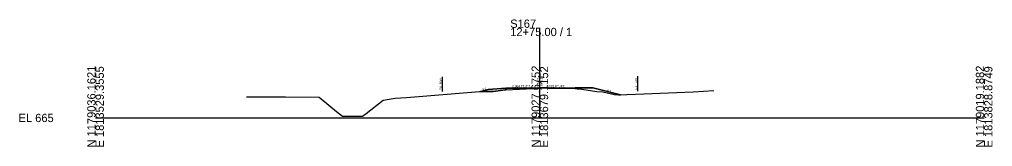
# Model space of a CAD drawing. Extents: x -26 to 6803, y -10 to 1023.
# Drawn here: x 3874.3 to 4202.8, y -9.7 to 33.3 of the extents above; entities that cross this region are included whole.
import ezdxf

# ---------------------------------------------------------------- set-up
doc = ezdxf.new("R2010")
doc.units = 0
for name, color, linetype in [('Default', 7, 'Continuous'), ('RD_EX_RW', 7, 'Continuous'), ('RD_GPK_XS_Cell', 7, 'Continuous'), ('RD_XS_EarthShd', 7, 'Continuous'), ('RD_XS_ExGround', 7, 'Continuous'), ('RD_XS_Misc_Line', 7, 'Continuous'), ('RD_XS_Pave', 7, 'Continuous'), ('RD_XS_TieSlope', 7, 'Continuous'), ('RD_XS_TX_Elev_EX', 7, 'Continuous'), ('RD_XS_TX_Elev_PR', 7, 'Continuous'), ('RD_XS_TX_Slope', 7, 'Continuous')]:
    doc.layers.add(name, color=color, linetype=linetype)

msp = doc.modelspace()

# ---------------------------------------------------------------- linework, layer by layer
at = {"layer": 'Default'}
for p, q in [((4038.52, 10.07), (4050, 10.12)), ((4050, 10.12), (4061.87, 10.14))]:
    msp.add_line(p, q, dxfattribs=at)
at = {"layer": 'RD_EX_RW'}
for p, q in [((4017, 13.91), (4017, 8.91)), ((4083, 14.09), (4083, 9.09))]:
    msp.add_line(p, q, dxfattribs=at)
at = {"layer": 'RD_GPK_XS_Cell'}
for p, q in [((4050, 0), (4050, 30.49)), ((3900, 0), (4050, 0)), ((4050, 0), (4200, 0))]:
    msp.add_line(p, q, dxfattribs=at)
at = {"layer": 'RD_XS_EarthShd'}
for p, q in [((4038.52, 10.07), (4032.52, 9.57)), ((4061.87, 10.14), (4067.87, 10.15))]:
    msp.add_line(p, q, dxfattribs=at)
at = {"layer": 'RD_XS_ExGround'}
msp.add_lwpolyline([(3950.93, 7.12), (3964.18, 7.11), (3975.5, 7.03), (3981.3, 2.14), (3983.41, 0.61), (3984.05, 0.61), (3987.19, 0.6), (3989.65, 0.62), (3990.1, 0.62), (3991.41, 1.46), (3997.14, 6.02), (4001.12, 6.66), (4004.95, 6.92), (4029.62, 8.94), (4034.2, 8.94), (4037.56, 9.36), (4038.52, 9.51), (4047.71, 10), (4050, 10.12), (4050.85, 10.16), (4053.57, 10.11), (4061.87, 9.96), (4062.58, 9.88), (4064.21, 9.69), (4069.22, 8.95), (4071.24, 8.78), (4075.26, 7.97), (4076.52, 7.76), (4085.13, 8.19), (4101.8, 8.78), (4108.71, 9.23)], dxfattribs=at)
at = {"layer": 'RD_XS_Misc_Line'}
for points in [[(4037.56, 9.36), (4038.52, 9.51), (4038.52, 10.07), (4032.52, 9.57), (4030.02, 8.94), (4034.2, 8.94)], [(4037.56, 9.36), (4038.52, 9.51), (4038.52, 10.07), (4032.52, 9.57), (4030.02, 8.94), (4034.2, 8.94)], [(4037.56, 9.36), (4038.52, 9.51), (4038.52, 10.07), (4032.52, 9.57), (4030.02, 8.94), (4034.2, 8.94)], [(4038.52, 10.07), (4038.52, 9.51), (4037.56, 9.36), (4034.2, 8.94), (4030.02, 8.94), (4032.52, 9.57)], [(4038.52, 10.07), (4038.52, 9.51), (4037.56, 9.36), (4034.2, 8.94), (4030.02, 8.94), (4032.52, 9.57)], [(4047.71, 10), (4050, 10.12), (4038.52, 10.07), (4038.52, 9.51)], [(4047.71, 10), (4050, 10.12), (4038.52, 10.07), (4038.52, 9.51)], [(4047.71, 10), (4050, 10.12), (4038.52, 10.07), (4038.52, 9.51)], [(4038.52, 10.07), (4038.52, 9.51), (4047.71, 10), (4050, 10.12)], [(4038.52, 10.07), (4038.52, 9.51), (4047.71, 10), (4050, 10.12)], [(4050, 10.12), (4050.85, 10.16), (4052.79, 10.12)], [(4050, 10.12), (4050.85, 10.16), (4052.79, 10.12)], [(4050, 10.12), (4050.85, 10.16), (4052.79, 10.12)], [(4050.85, 10.16), (4052.79, 10.12), (4050, 10.12)], [(4050.85, 10.16), (4052.79, 10.12), (4050, 10.12)], [(4052.79, 10.12), (4061.87, 10.14), (4061.87, 9.96), (4053.57, 10.11)], [(4052.79, 10.12), (4061.87, 10.14), (4061.87, 9.96), (4053.57, 10.11)], [(4052.79, 10.12), (4061.87, 10.14), (4061.87, 9.96), (4053.57, 10.11)], [(4052.79, 10.12), (4053.57, 10.11), (4061.87, 9.96), (4061.87, 10.14)], [(4052.79, 10.12), (4053.57, 10.11), (4061.87, 9.96), (4061.87, 10.14)], [(4075.26, 7.97), (4076.52, 7.76), (4077.26, 7.8), (4067.87, 10.15), (4061.87, 10.14), (4061.87, 9.96), (4062.58, 9.88), (4064.21, 9.69), (4069.22, 8.95), (4071.24, 8.78)], [(4075.26, 7.97), (4076.52, 7.76), (4077.26, 7.8), (4067.87, 10.15), (4061.87, 10.14), (4061.87, 9.96), (4062.58, 9.88), (4064.21, 9.69), (4069.22, 8.95), (4071.24, 8.78)], [(4075.26, 7.97), (4076.52, 7.76), (4077.26, 7.8), (4067.87, 10.15), (4061.87, 10.14), (4061.87, 9.96), (4062.58, 9.88), (4064.21, 9.69), (4069.22, 8.95), (4071.24, 8.78)], [(4061.87, 9.96), (4062.58, 9.88), (4064.21, 9.69), (4069.22, 8.95), (4071.24, 8.78), (4075.26, 7.97), (4076.52, 7.76), (4077.26, 7.8), (4067.87, 10.15), (4061.87, 10.14)], [(4061.87, 9.96), (4062.58, 9.88), (4064.21, 9.69), (4069.22, 8.95), (4071.24, 8.78), (4075.26, 7.97), (4076.52, 7.76), (4077.26, 7.8), (4067.87, 10.15), (4061.87, 10.14)]]:
    msp.add_lwpolyline(points, close=True, dxfattribs=at)
at = {"layer": 'RD_XS_Pave'}
for p, q in [((4038.52, 10.07), (4038.52, 9.51)), ((4061.87, 9.96), (4061.87, 10.14))]:
    msp.add_line(p, q, dxfattribs=at)
at = {"layer": 'RD_XS_TieSlope'}
for p, q in [((4067.87, 10.15), (4077.26, 7.8)), ((4032.52, 9.57), (4030.02, 8.94))]:
    msp.add_line(p, q, dxfattribs=at)

# ---------------------------------------------------------------- texts
at = {"layer": 'RD_EX_RW'}
for p in [(4016.94, 9.43), (4082.94, 9.61)]:
    msp.add_text('EX. R/W', height=0.75, rotation=90, dxfattribs=at).set_placement(p)
at = {"layer": 'RD_GPK_XS_Cell'}
for s, p in [('S167', (4040, 30.49)), ('12+75.00 / 1', (4040, 27.69)), ('EL 665', (3874, -1.4))]:
    msp.add_text(s, height=2.8, dxfattribs=at).set_placement(p)
for s, p in [('N 1179036.1621', (3900, -10)), ('E 1813529.3555', (3902.8, -10)), ('N 1179027.6752', (4050, -10)), ('E 1813679.1152', (4052.8, -10)), ('N 1179019.1882', (4200, -10)), ('E 1813828.8749', (4202.8, -10))]:
    msp.add_text(s, height=2.8, rotation=90, dxfattribs=at).set_placement(p)
at = {"layer": 'RD_XS_TX_Elev_EX'}
msp.add_text('675.12', height=0.8, rotation=90, dxfattribs=at).set_placement((4049.86, 10.18))
at = {"layer": 'RD_XS_TX_Elev_PR'}
msp.add_text('675.12', height=0.8, rotation=90, dxfattribs=at).set_placement((4050.93, 10.82))
at = {"layer": 'RD_XS_TX_Slope'}
for s, rotation, p in [('4:1', 14.0362, (4030.64, 9.32)), ('0.004 FT./FT.', 0.2521, (4040.69, 10.33)), ('0.002 FT./FT.', 0.0917, (4052.3, 10.37)), ('4:1', 345.9638, (4072.6, 9.03))]:
    msp.add_text(s, height=0.75, rotation=rotation, dxfattribs=at).set_placement(p)

doc.saveas('drawing.dxf')
